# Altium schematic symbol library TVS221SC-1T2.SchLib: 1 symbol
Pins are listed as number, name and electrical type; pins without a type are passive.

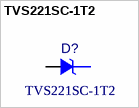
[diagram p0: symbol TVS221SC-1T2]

## TVS221SC-1T2
designator D?
footprint ST_SOD882_CSPS
pins: 1 K, 2 A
